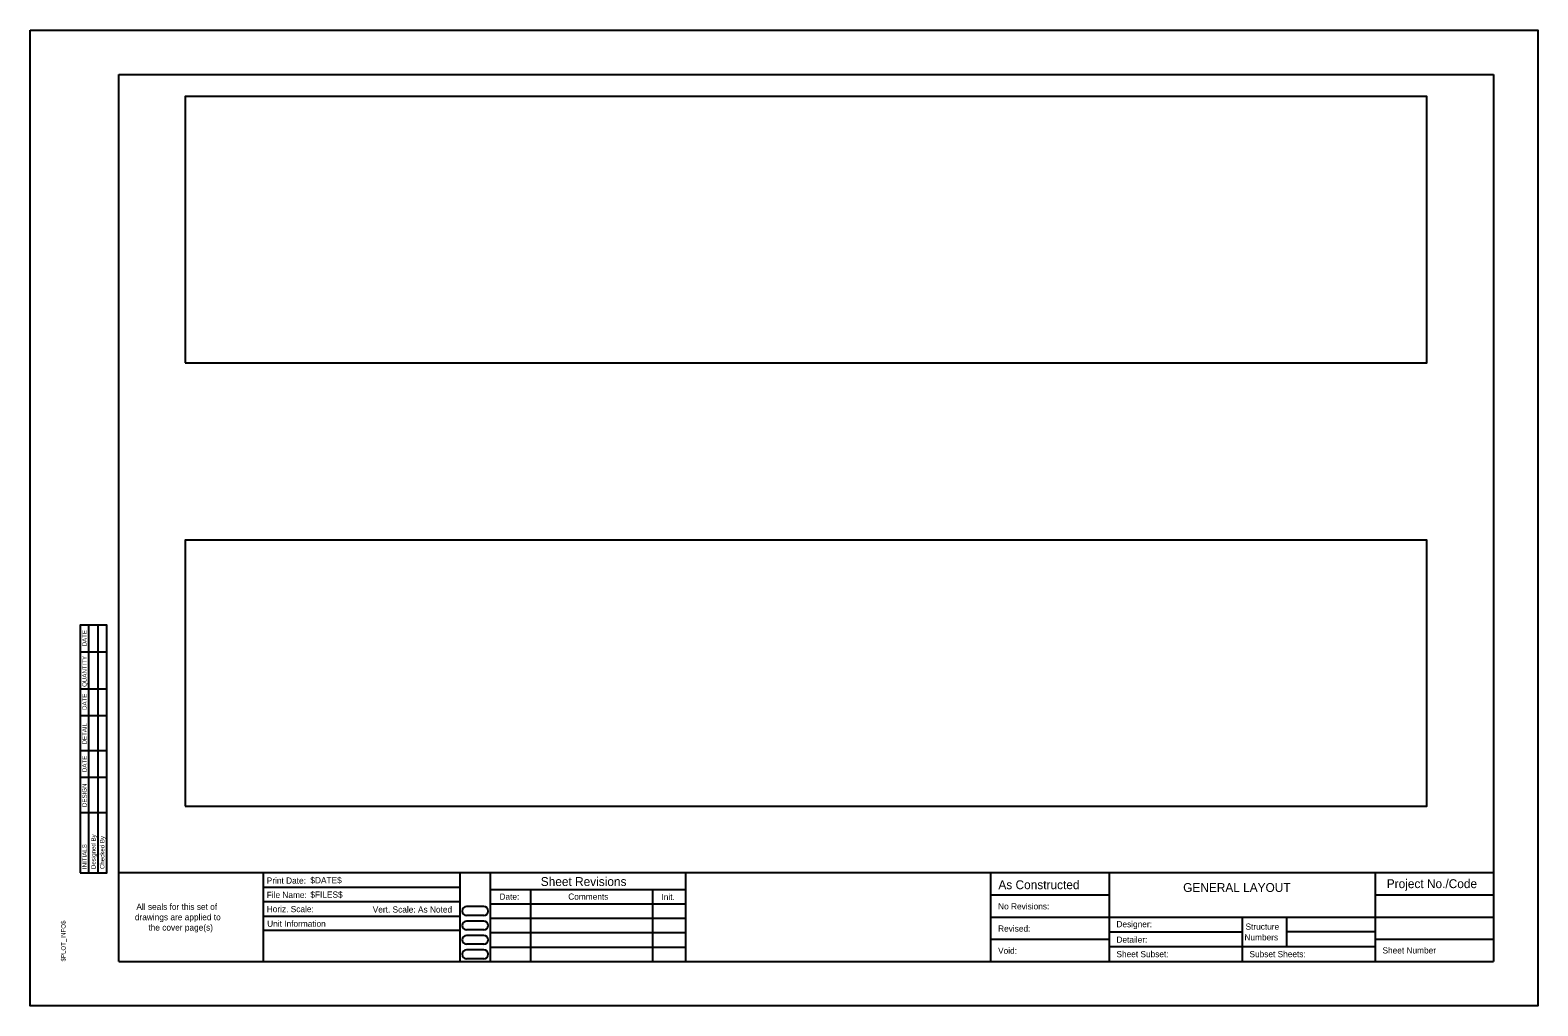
# Model space of a CAD drawing. Extents: x 0 to 1.42, y 0 to 0.92.
import ezdxf

# ---------------------------------------------------------------- set-up
doc = ezdxf.new("R2010")
doc.units = 0
for name, color, linetype in [('DRAFT_Information-No Plot', 7, 'Continuous'), ('SHEET_Lines', 7, 'Continuous'), ('SHEET_Plot Boundary', 7, 'Continuous'), ('SHEET_Text-Border Info', 7, 'Continuous'), ('SHEET_Text-Titles', 7, 'Continuous')]:
    doc.layers.add(name, color=color, linetype=linetype)

msp = doc.modelspace()

# ---------------------------------------------------------------- linework, layer by layer
at = {"layer": 'DRAFT_Information-No Plot'}
for points in [[(0.1458, 0.6042), (1.3125, 0.6042), (1.3125, 0.8542), (0.1458, 0.8542)], [(0.1458, 0.1875), (1.3125, 0.1875), (1.3125, 0.4375), (0.1458, 0.4375)]]:
    msp.add_lwpolyline(points, close=True, dxfattribs=at)
at = {"layer": 'SHEET_Lines'}
for p, q in [((0.0833, 0.875), (1.375, 0.875)), ((0.0833, 0.0417), (0.0833, 0.875)), ((1.375, 0.875), (1.375, 0.0417)), ((0.0552, 0.125), (0.0552, 0.3576)), ((0.0635, 0.3576), (0.0635, 0.125)), ((0.0469, 0.3326), (0.0719, 0.3326)), ((0.0469, 0.2979), (0.0719, 0.2979)), ((0.0469, 0.2729), (0.0719, 0.2729)), ((0.0719, 0.2396), (0.0469, 0.2396)), ((0.0719, 0.2146), (0.0469, 0.2146)), ((0.0719, 0.1813), (0.0469, 0.1813)), ((1.375, 0.125), (0.0833, 0.125)), ((0.2188, 0.125), (0.2188, 0.0417)), ((0.4042, 0.0417), (0.4042, 0.125)), ((0.4324, 0.0417), (0.4324, 0.125)), ((0.616, 0.0417), (0.616, 0.125)), ((0.9028, 0.0417), (0.9028, 0.125)), ((1.0139, 0.125), (1.0139, 0.0417)), ((1.2639, 0.125), (1.2639, 0.0417)), ((0.2188, 0.1115), (0.4042, 0.1115)), ((0.4324, 0.1094), (0.616, 0.1094)), ((0.4706, 0.0417), (0.4706, 0.1094)), ((0.5852, 0.0417), (0.5852, 0.1094)), ((0.9028, 0.1042), (1.0139, 0.1042)), ((1.2639, 0.1042), (1.375, 0.1042)), ((0.2188, 0.098), (0.4042, 0.098)), ((0.4264, 0.0932), (0.41, 0.0932)), ((0.4324, 0.0958), (0.616, 0.0958)), ((0.2188, 0.0844), (0.4042, 0.0844)), ((0.4042, 0.0709), (0.2188, 0.0709)), ((0.4264, 0.085), (0.41, 0.085)), ((0.4264, 0.0796), (0.41, 0.0796)), ((0.4264, 0.0714), (0.41, 0.0714)), ((0.4324, 0.0823), (0.616, 0.0823)), ((0.9028, 0.0833), (1.375, 0.0833)), ((1.1389, 0.0833), (1.1389, 0.0417)), ((1.1806, 0.0833), (1.1806, 0.0556)), ((0.4264, 0.0661), (0.41, 0.0661)), ((0.4264, 0.0579), (0.41, 0.0579)), ((0.4324, 0.0688), (0.616, 0.0688)), ((0.9028, 0.0625), (1.0139, 0.0625)), ((1.0139, 0.0694), (1.1389, 0.0694)), ((1.2639, 0.0694), (1.1806, 0.0694)), ((1.2639, 0.0625), (1.375, 0.0625)), ((0.4264, 0.0525), (0.41, 0.0525)), ((0.4264, 0.0443), (0.41, 0.0443)), ((0.4324, 0.0552), (0.616, 0.0552)), ((1.0139, 0.0556), (1.2639, 0.0556)), ((0.0833, 0.0417), (1.375, 0.0417))]:
    msp.add_line(p, q, dxfattribs=at)
msp.add_lwpolyline([(0.0469, 0.125), (0.0719, 0.125), (0.0719, 0.3576), (0.0469, 0.3576)], close=True, dxfattribs=at)
for centre, start, end in [((0.41, 0.0891), 90, 270), ((0.4264, 0.0891), 270, 90), ((0.41, 0.0755), 90, 270), ((0.4264, 0.0755), 270, 90), ((0.41, 0.062), 90, 270), ((0.4264, 0.062), 270, 90), ((0.41, 0.0484), 90, 270), ((0.4264, 0.0484), 270, 90)]:
    msp.add_arc(centre, 0.00409, start, end, dxfattribs=at)
at = {"layer": 'SHEET_Plot Boundary'}
msp.add_lwpolyline([(0, 0.9167), (1.4167, 0.9167), (1.4167, 0), (0, 0)], close=True, dxfattribs=at)

# ---------------------------------------------------------------- texts
at = {"layer": 'SHEET_Text-Border Info'}
for s, height, p in [('DATE', 0.00417, (0.0531, 0.3377)), ('QUANTITY', 0.00417, (0.0531, 0.2997)), ('DATE', 0.00417, (0.0531, 0.278)), ('DETAIL', 0.00417, (0.0531, 0.2456)), ('DATE', 0.00417, (0.0531, 0.2196)), ('DESIGN', 0.00417, (0.0531, 0.1868)), ('Designed By', 0.004167, (0.0615, 0.1285)), ('Checked By', 0.00417, (0.0698, 0.1285)), ('INITIALS', 0.00417, (0.0531, 0.1285)), ('$PLOT_INFO$', 0.004167, (0.0333, 0.0417))]:
    msp.add_text(s, height=height, rotation=90, dxfattribs=at).set_placement(p)
for s, height, p in [('Print Date:', 0.005833, (0.2223, 0.1148)), ('$DATE$', 0.00583, (0.2633, 0.1151)), ('File Name:', 0.00583, (0.2223, 0.1013)), ('$FILES$', 0.00583, (0.2633, 0.1016)), ('Date:', 0.00583, (0.441, 0.0997)), ('Comments', 0.00583, (0.5056, 0.0997)), ('Init.', 0.00583, (0.5932, 0.0994)), ('drawings are applied to', 0.005833, (0.0984, 0.0804)), ('All seals for this set of', 0.005833, (0.0998, 0.0902)), ('Horiz. Scale:', 0.005833, (0.2223, 0.088)), ('Vert. Scale: As Noted', 0.005833, (0.3219, 0.0876)), ('No Revisions:', 0.005833, (0.9095, 0.0906)), ('the cover page(s)', 0.005833, (0.1111, 0.0707)), ('Unit Information', 0.005833, (0.2227, 0.0743)), ('Revised:', 0.00583, (0.9095, 0.0697)), ('Designer:', 0.00583, (1.0207, 0.0738)), ('Structure', 0.00583, (1.142, 0.0715)), ('Detailer:', 0.00583, (1.0207, 0.0593)), ('Numbers', 0.00583, (1.141, 0.0615)), ('Void:', 0.00583, (0.9095, 0.0489)), ('Sheet Subset:', 0.005833, (1.0207, 0.0457)), ('Subset Sheets:', 0.005833, (1.1457, 0.0457)), ('Sheet Number', 0.005833, (1.2707, 0.0492))]:
    msp.add_text(s, height=height, dxfattribs=at).set_placement(p)
at = {"layer": 'SHEET_Text-Titles'}
for s, p in [('Sheet Revisions', (0.4798, 0.1126)), ('As Constructed', (0.9098, 0.1096)), ('GENERAL LAYOUT', (1.0834, 0.107)), ('Project No./Code', (1.2747, 0.1106))]:
    msp.add_text(s, height=0.008333, dxfattribs=at).set_placement(p)

doc.saveas('drawing.dxf')
